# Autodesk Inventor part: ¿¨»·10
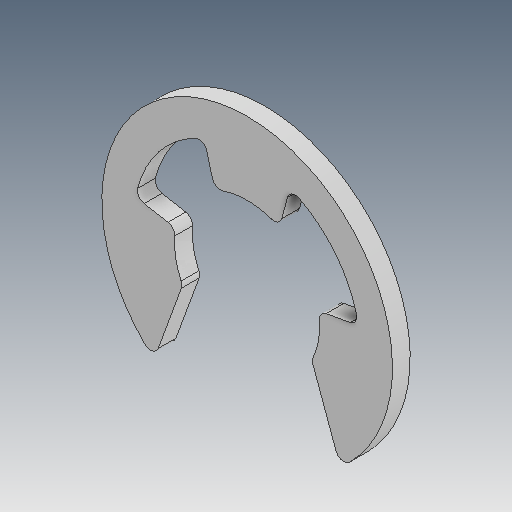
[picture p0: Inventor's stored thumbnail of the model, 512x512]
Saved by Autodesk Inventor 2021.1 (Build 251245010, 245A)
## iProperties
Created: 2013-04
Part Number: ¿¨»·10
Material: Ogólny
Document SubType Name: Modeling
Designer: user
Density: 1 g/cm^3
Appearance: Domyślna
Author: user
Revision Number: ÈÎºÎ
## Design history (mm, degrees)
feature "Í¹Ì¨-À­Éì1"
node "Bryła1"
